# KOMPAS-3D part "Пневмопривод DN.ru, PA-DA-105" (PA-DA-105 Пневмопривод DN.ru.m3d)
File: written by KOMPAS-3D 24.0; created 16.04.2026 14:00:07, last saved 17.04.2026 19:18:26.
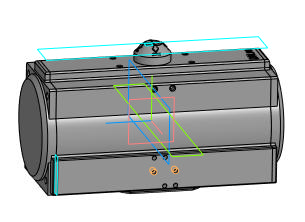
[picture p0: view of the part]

Document properties: Автор: DN.ru; Полное имя файла: C:\Работа\PA-DA-х Пневмопривод DN.ru\105\исходные материалы\PA-DA-105 Пневмопривод DN.ru.m3d

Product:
- Body: Тело 1  | qty 1
    Масса: 28.435725
- Body: Тело 2  | qty 1
    Масса: 28.435725
- Part/product: Пневмопривод DN.ru  | designation PA-DA-105
    Масса: 6.8
    Раздел спецификации: Прочие изделия
    Примечание: D290-00296

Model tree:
1. Эскиз:1
2. Элемент выдавливания:1
3. Эскиз:2  (with: Ребро.Элемент выдавливания:1)
4. Элемент выдавливания:2
5. Эскиз:3  (with: Ребро.Элемент выдавливания:2)
6. Элемент выдавливания:3  (with: Грань.Элемент выдавливания:2)
     Смещение 1 = -2; Расстояние 2 = 124.5; Смещение 2 = -2
7. Эскиз:4  (with: Грань.Элемент выдавливания:3, Ребро.Элемент выдавливания:3)
8. Элемент выдавливания:4
9. Эскиз:6  (with: Ребро.Элемент выдавливания:2)
10. Элемент выдавливания:6
11. Отверстие:2  (with: Грань.Элемент выдавливания:6)
     Глубина выреза = 10; Диаметр отверстия = 5; Угол конуса дна = 120; Расстояние 2 = 4
12. Массив по сетке:2  (with: Отверстие:2)  (3 pattern instances)
     Шаг 1 = 12; Угол раствора = 90; Шаг 2 = 32
13. Массив по сетке:3  (with: Отверстие:2)  (2 pattern instances)
     Шаг 1 = 32; Угол раствора = 90; Шаг 2 = 12
14. Отверстие:3  (with: Грань.Элемент выдавливания:6, Ребро.Элемент выдавливания:6)  (labels: W 1/4'')
     Глубина выреза = 10; Диаметр отверстия = 4.72357; Угол конуса дна = 120; Расстояние 1 = 12; Расстояние 2 = 20
15. W 1/4''  (with: Грань.Отверстие:3, Грань.Элемент выдавливания:6)  (labels: cil5_ex_DIN 477 BSW coarse)
     Длина резьбы = 8; Шаг резьбы = 1.27; Номинальный диаметр резьбы = 6.35
16. Массив по сетке:4  (with: Отверстие:3)  (labels: W 1/4'')  (2 pattern instances)
17. Эскиз:7  (with: Грань.Элемент выдавливания:2)
18. Элемент выдавливания:7
19. Эскиз:8  (with: Грань.Элемент выдавливания:2, Ребро.Элемент выдавливания:2)
20. Элемент выдавливания:8  (with: Грань.Элемент выдавливания:6)
     Расстояние 2 = 4
21. Отверстие:4  (with: Грань.Элемент выдавливания:2)
     Глубина выреза = 7; Диаметр отверстия = 5; Угол конуса дна = 118; Расстояние 1 = 6; Расстояние 2 = 10; Диаметр зенковки = 7; Глубина зенковки = 1; Угол зенковки = 90
22. Массив по сетке:5  (with: Отверстие:4)  (2 pattern instances)
     Шаг 1 = 20; Угол раствора = 90
23. Отверстие:5  (with: Грань.Элемент выдавливания:3)
     Глубина выреза = 10; Диаметр отверстия = 5; Угол конуса дна = 120; Диаметр зенковки = 7; Глубина зенковки = 1; Угол зенковки = 90
24. Массив по сетке:6  (with: Отверстие:5)  (4 pattern instances)
     Угол раствора = 90
25. Фаска:1  (with: Ребро.Элемент выдавливания:4)
     Угол = 45; Длина 1 = 10; Длина 2 = 10
26. Скругление:2  (with: Ребро.Элемент выдавливания:3)
     Радиус = 2
27. Скругление:3  (with: Ребро.Элемент выдавливания:6)
     Радиус = 2
28. Скругление:4  (with: Ребро.Элемент выдавливания:8, Ребро.Элемент выдавливания:2)
     Радиус = 2
29. Скругление:5  (with: Ребро.Элемент выдавливания:6)
     Радиус = 1
30. Смещенная плоскость:1  (with: Грань.Элемент выдавливания:3)
31. Эскиз:9
32. Элемент выдавливания:9  (with: Грань.Фаска:1)
     Расстояние 1 = 17.4142; Смещение 1 = 1
33. Смещенная плоскость:2  (with: Грань.Элемент выдавливания:4)
     Расстояние = 0.5
34. Эскиз:10
35. Элемент выдавливания:10
     Расстояние 1 = 10.9142
36. Эскиз:11  (with: Грань.Элемент выдавливания:4)
37. Элемент выдавливания:11
     Расстояние 1 = 1
38. Эскиз:12  (with: Грань.Элемент выдавливания:11)
39. Элемент выдавливания:12  (with: Грань.Элемент выдавливания:4)
     Расстояние 2 = 1
40. Эскиз:13  (with: Грань.Элемент выдавливания:11)
41. Элемент выдавливания:13  (with: Грань.Элемент выдавливания:4)
     Расстояние 2 = 1
42. Скругление:7  (with: Ребро.Элемент выдавливания:11)
     Радиус = 1
43. Скругление:8  (with: Ребро.Элемент выдавливания:2, Ребро.Элемент выдавливания:8)
     Радиус = 2
44. Эскиз:14  (with: Грань.Элемент выдавливания:3)
45. Элемент выдавливания:14  (with: Грань.Фаска:1)
     Расстояние 1 = 29.1414; Смещение 1 = 0.1
46. Эскиз:15  (with: Грань.Элемент выдавливания:3, Ребро.Скругление:2)
47. Элемент выдавливания:15
     Расстояние 2 = 0.1
48. Отверстие:6  (with: Грань.Элемент выдавливания:2, Ребро.Элемент выдавливания:2)
     Глубина выреза = 10; Диаметр отверстия = 8; Угол конуса дна = 118; Расстояние 1 = 10; Расстояние 2 = 10
49. Зеркальный массив:1
50. Экземпляр ( 1 )
51. Экземпляр ( 2 )  (with: Отверстие:6)
52. Зеркальный массив:2  (with: Экземпляр ( 1 ), Экземпляр ( 2 ), Отверстие:6)
53. Зеркальный массив:3  (with: Экземпляр ( 1 ), Экземпляр ( 2 ), Зеркальный массив:2, Отверстие:6)
54. Зеркальный массив:4  (with: Экземпляр ( 1 ), Экземпляр ( 2 ), Зеркальный массив:1, Отверстие:6, Зеркальный массив:3, Зеркальный массив:2)
55. Фаска:2  (with: Ребро.Элемент выдавливания:7)
     Угол = 45; Длина 1 = 1.6; Длина 2 = 1.6
56. Фаска:3  (with: Ребро.Элемент выдавливания:1)
     Угол = 45; Длина 1 = 5; Длина 2 = 5
57. Смещенная плоскость:3  (with: Грань.Элемент выдавливания:6)
     Расстояние = 5
58. Эскиз:16
59. Элемент выдавливания:16
     Расстояние 2 = 0.1
60. Зеркальный массив:5  (with: Экземпляр ( 1 ), Экземпляр ( 2 ), Элемент выдавливания:16)

Expressions: H/2; -G/2; (E-C-4.5)/2
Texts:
  PA-DA-105
  GOST 26.020 Pr3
